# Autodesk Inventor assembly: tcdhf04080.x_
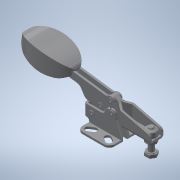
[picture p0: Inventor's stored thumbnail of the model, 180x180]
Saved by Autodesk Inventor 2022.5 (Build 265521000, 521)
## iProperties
Part Number: tcdhf04080.x_
Material: 一般
Document SubType Name: Assembly
Designer: ImaoCorp
Sending System: SOLIDWORKS 2017-2017317
MC: AMD64
MC_MODEL: Intel64 Family 6 Model 60 Stepping 3, GenuineIntel
OS: Windows_NT
FRU: Parasolid Version 29.0, build 201,  4-17-2017
FORMAT: text
GUISE: transmit
KEY: tcdhf04080
FILE: tcdhf04080.x_t
DATE: Wed Sep 18 16:31:21 2019
Author: ImaoCorp
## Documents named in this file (8)
- X:\14_SW2022-Inv2022\00_全2023-1023新製品(TCC)まで\t\tcdhf04080\TCDHF04080.iam
- X:\14_SW2022-Inv2022\00_全2023-1023新製品(TCC)まで\t\tcdhf04080\tcdhf04080_01.ipt
- X:\14_SW2022-Inv2022\00_全2023-1023新製品(TCC)まで\t\tcdhf04080\tcdhf04080_02.ipt
- X:\14_SW2022-Inv2022\00_全2023-1023新製品(TCC)まで\t\tcdhf04080\tcdhf04080_03.ipt
- X:\14_SW2022-Inv2022\00_全2023-1023新製品(TCC)まで\t\tcdhf04080\tcdhf04080_04.ipt
- X:\14_SW2022-Inv2022\00_全2023-1023新製品(TCC)まで\t\tcdhf04080\tcdhf04080_05.ipt
- X:\14_SW2022-Inv2022\00_全2023-1023新製品(TCC)まで\t\tcdhf04080\tcdhf04080_06.ipt
- X:\14_SW2022-Inv2022\00_全2023-1023新製品(TCC)まで\t\tcdhf04080\tcdhf04080_07.ipt
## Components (7 placed, 7 different names)
1. tcdhf04080_01
2. tcdhf04080_02
3. tcdhf04080_03
4. tcdhf04080_04
5. tcdhf04080_05
6. tcdhf04080_06
7. tcdhf04080_07
